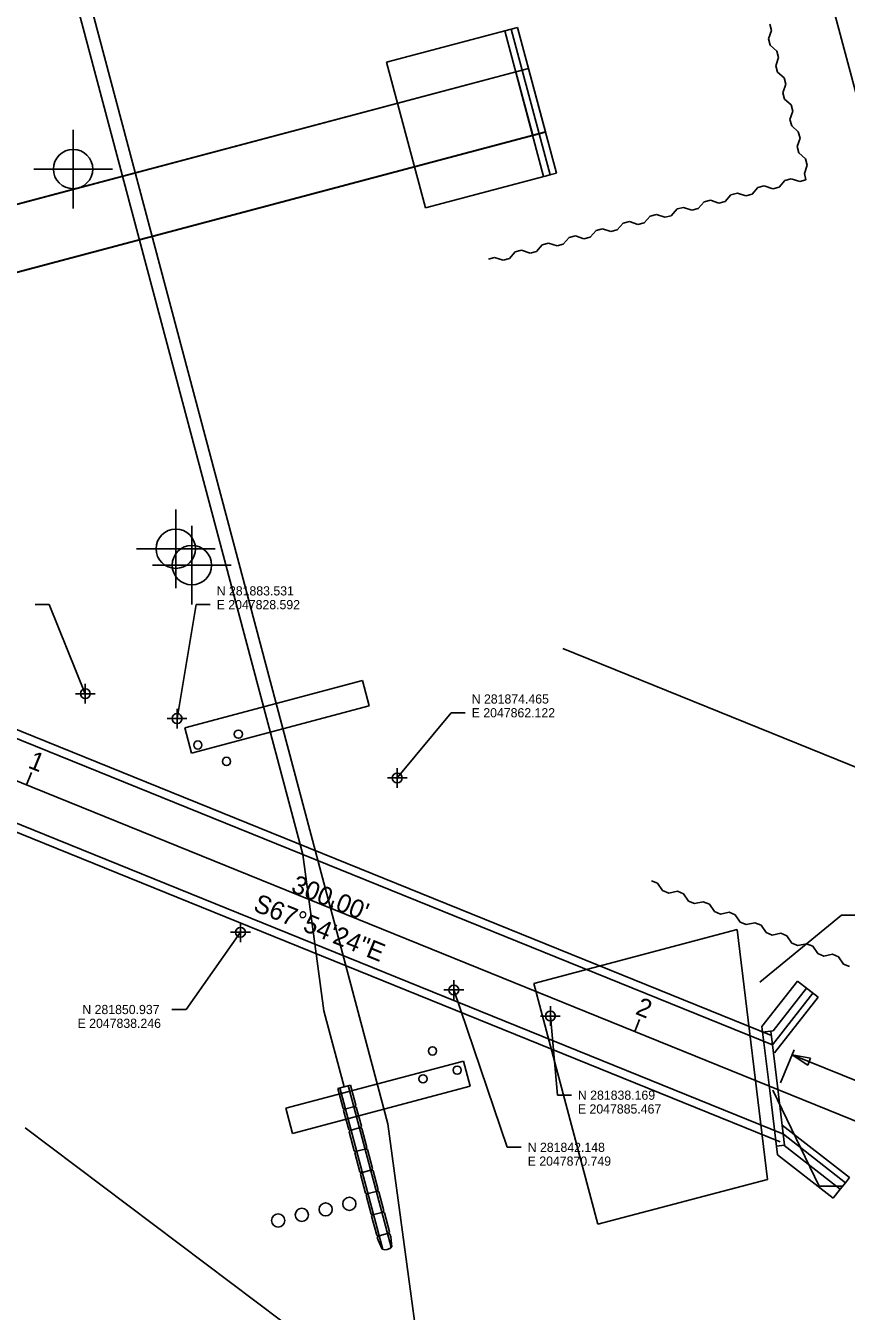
# Model space of a CAD drawing. Extents: x 2047712 to 2051245, y 280285 to 283042.
# Drawn here: x 2047805.5 to 2047930.5, y 281793.2 to 281989.1 of the extents above; entities that cross this region are included whole.
import ezdxf

# ---------------------------------------------------------------- set-up
doc = ezdxf.new("R2010")
doc.units = 0
for name, color, linetype in [('DV_X_Property_Line', 7, 'Continuous'), ('DV_X_Text', 7, 'Continuous'), ('RD_X_Cells', 7, 'Continuous'), ('RD_X_Concrete_Pad', 7, 'Continuous'), ('RD_X_GR_Lt', 7, 'Continuous'), ('RD_X_GR_Rt', 7, 'Continuous'), ('RW_X_CL_100_Cardinal_Points', 7, 'Continuous'), ('RW_X_CL_100_Curve_Data', 7, 'Continuous'), ('RW_X_CL_100_Distances', 7, 'Continuous'), ('RW_X_Esmt_SH', 7, 'Continuous'), ('SC_Scratch1', 7, 'Continuous'), ('SH_Data', 7, 'Continuous'), ('SV_Control_Point', 7, 'Continuous'), ('SV_X_Mon_Cells_Found', 7, 'Continuous'), ('SV_X_Text', 7, 'Continuous'), ('TopoDOT_Transients', 7, 'Continuous')]:
    doc.layers.add(name, color=color, linetype=linetype)

msp = doc.modelspace()

# ---------------------------------------------------------------- linework, layer by layer
at = {"layer": 'RD_X_Cells'}
for p, q in [((2047805.64, 281873.43), (2047806.39, 281875.28)), ((2047851.97, 281854.62), (2047852.42, 281855.74)), ((2047898.3, 281835.82), (2047899.05, 281837.67))]:
    msp.add_line(p, q, dxfattribs=at)
at = {"layer": 'RD_X_Concrete_Pad'}
for p, q in [((2047809.11, 281900.89), (2047806.97, 281900.89)), ((2047809.11, 281900.89), (2047814.61, 281887.31)), ((2047828.59, 281883.53), (2047831.51, 281900.89)), ((2047831.51, 281900.89), (2047833.65, 281900.89)), ((2047862.12, 281874.47), (2047870.36, 281884.41)), ((2047870.36, 281884.41), (2047872.5, 281884.41)), ((2047917.37, 281843.35), (2047929.82, 281853.53)), ((2047933.35, 281853.53), (2047929.82, 281853.53)), ((2047829.95, 281839.17), (2047838.25, 281850.94)), ((2047878.89, 281818.16), (2047870.75, 281842.15)), ((2047829.95, 281839.17), (2047827.81, 281839.17)), ((2047886.54, 281826.11), (2047885.47, 281838.17)), ((2047919.37, 281826.89), (2047926.42, 281812.25)), ((2047886.54, 281826.11), (2047888.68, 281826.11)), ((2047878.89, 281818.16), (2047881.03, 281818.16)), ((2047929.94, 281812.25), (2047926.42, 281812.25))]:
    msp.add_line(p, q, dxfattribs=at)
at = {"layer": 'RD_X_GR_Lt'}
for p, q in [((2047828.39, 281909.42), (2047828.39, 281915.42)), ((2047828.39, 281912.42), (2047828.39, 281909.42)), ((2047828.39, 281909.42), (2047822.39, 281909.42)), ((2047828.39, 281909.42), (2047825.39, 281909.42)), ((2047828.39, 281909.42), (2047828.39, 281903.42)), ((2047828.39, 281909.42), (2047834.39, 281909.42)), ((2047828.39, 281906.42), (2047828.39, 281909.42)), ((2047828.39, 281909.42), (2047831.39, 281909.42)), ((2047814.61, 281887.31), (2047814.61, 281888.81)), ((2047814.61, 281888.06), (2047814.61, 281887.31)), ((2047814.61, 281887.31), (2047813.11, 281887.31)), ((2047814.61, 281887.31), (2047813.86, 281887.31)), ((2047814.61, 281887.31), (2047814.61, 281885.81)), ((2047814.61, 281887.31), (2047816.11, 281887.31)), ((2047814.61, 281886.56), (2047814.61, 281887.31)), ((2047814.61, 281887.31), (2047815.36, 281887.31)), ((2047828.59, 281883.53), (2047828.59, 281885.03)), ((2047828.59, 281884.28), (2047828.59, 281883.53)), ((2047828.59, 281883.53), (2047827.09, 281883.53)), ((2047828.59, 281883.53), (2047827.84, 281883.53)), ((2047828.59, 281883.53), (2047828.59, 281882.03)), ((2047828.59, 281883.53), (2047830.09, 281883.53)), ((2047828.59, 281882.78), (2047828.59, 281883.53)), ((2047828.59, 281883.53), (2047829.34, 281883.53)), ((2047862.12, 281874.47), (2047862.12, 281875.97)), ((2047862.12, 281874.47), (2047860.62, 281874.47)), ((2047862.12, 281874.47), (2047861.37, 281874.47)), ((2047862.12, 281875.22), (2047862.12, 281874.47)), ((2047862.12, 281874.47), (2047862.12, 281872.97)), ((2047862.12, 281874.47), (2047863.62, 281874.47)), ((2047862.12, 281873.72), (2047862.12, 281874.47)), ((2047862.12, 281874.47), (2047862.87, 281874.47))]:
    msp.add_line(p, q, dxfattribs=at)
for centre, radius in [((2047828.39, 281909.42), 3), ((2047814.61, 281887.31), 0.75), ((2047828.59, 281883.53), 0.75), ((2047862.12, 281874.47), 0.75)]:
    msp.add_circle(centre, radius, dxfattribs=at)
for centre, radius, start, end in [((2047828.39, 281909.42), 3, 90, 180), ((2047828.39, 281909.42), 3, 270, 360), ((2047814.61, 281887.31), 0.75, 90, 180), ((2047814.61, 281887.31), 0.75, 270, 360), ((2047828.59, 281883.53), 0.75, 90, 180), ((2047828.59, 281883.53), 0.75, 270, 360), ((2047862.12, 281874.47), 0.75, 90, 180), ((2047862.12, 281874.47), 0.75, 270, 360)]:
    msp.add_arc(centre, radius, start, end, dxfattribs=at)
at = {"layer": 'RD_X_GR_Rt'}
for p, q in [((2047887.35, 281894.22), (2048031.58, 281835.68)), ((2047920.53, 281827.98), (2047922.58, 281833.03)), ((2047922.28, 281832.28), (2048014.94, 281794.67))]:
    msp.add_line(p, q, dxfattribs=at)
msp.add_lwpolyline([(2047925.08, 281831.75), (2047924.66, 281830.71), (2047922.28, 281832.28)], close=True, dxfattribs=at)
at = {"layer": 'RW_X_CL_100_Cardinal_Points'}
for p, q in [((2047812.74, 281967.3), (2047812.74, 281973.3)), ((2047812.74, 281970.3), (2047812.74, 281967.3)), ((2047812.74, 281967.3), (2047806.74, 281967.3)), ((2047812.74, 281967.3), (2047809.74, 281967.3)), ((2047812.74, 281967.3), (2047812.74, 281961.3)), ((2047812.74, 281967.3), (2047818.74, 281967.3)), ((2047812.74, 281964.3), (2047812.74, 281967.3)), ((2047812.74, 281967.3), (2047815.74, 281967.3)), ((2047830.84, 281906.92), (2047830.84, 281912.92)), ((2047830.84, 281909.92), (2047830.84, 281906.92)), ((2047830.84, 281906.92), (2047824.84, 281906.92)), ((2047830.84, 281906.92), (2047827.84, 281906.92)), ((2047830.84, 281906.92), (2047830.84, 281900.92)), ((2047830.84, 281906.92), (2047836.84, 281906.92)), ((2047830.84, 281903.92), (2047830.84, 281906.92)), ((2047830.84, 281906.92), (2047833.84, 281906.92)), ((2047838.25, 281850.94), (2047838.25, 281852.44)), ((2047838.25, 281850.94), (2047836.75, 281850.94)), ((2047838.25, 281850.94), (2047837.5, 281850.94)), ((2047838.25, 281851.69), (2047838.25, 281850.94)), ((2047838.25, 281850.94), (2047838.25, 281849.44)), ((2047838.25, 281850.94), (2047839.75, 281850.94)), ((2047838.25, 281850.19), (2047838.25, 281850.94)), ((2047838.25, 281850.94), (2047839, 281850.94)), ((2047870.75, 281842.15), (2047870.75, 281843.65)), ((2047870.75, 281842.9), (2047870.75, 281842.15)), ((2047870.75, 281842.15), (2047869.25, 281842.15)), ((2047870.75, 281842.15), (2047870, 281842.15)), ((2047870.75, 281842.15), (2047870.75, 281840.65)), ((2047870.75, 281842.15), (2047872.25, 281842.15)), ((2047870.75, 281841.4), (2047870.75, 281842.15)), ((2047870.75, 281842.15), (2047871.5, 281842.15)), ((2047885.47, 281838.17), (2047885.47, 281839.67)), ((2047885.47, 281838.92), (2047885.47, 281838.17)), ((2047885.47, 281838.17), (2047883.97, 281838.17)), ((2047885.47, 281838.17), (2047884.72, 281838.17)), ((2047885.47, 281838.17), (2047885.47, 281836.67)), ((2047885.47, 281838.17), (2047886.97, 281838.17)), ((2047885.47, 281837.42), (2047885.47, 281838.17)), ((2047885.47, 281838.17), (2047886.22, 281838.17))]:
    msp.add_line(p, q, dxfattribs=at)
for centre, radius in [((2047812.74, 281967.3), 3), ((2047830.84, 281906.92), 3), ((2047838.25, 281850.94), 0.75), ((2047870.75, 281842.15), 0.75), ((2047885.47, 281838.17), 0.75)]:
    msp.add_circle(centre, radius, dxfattribs=at)
for centre, radius, start, end in [((2047812.74, 281967.3), 3, 90, 180), ((2047812.74, 281967.3), 3, 270, 360), ((2047830.84, 281906.92), 3, 90, 180), ((2047830.84, 281906.92), 3, 270, 360), ((2047838.25, 281850.94), 0.75, 90, 180), ((2047838.25, 281850.94), 0.75, 270, 360), ((2047870.75, 281842.15), 0.75, 90, 180), ((2047870.75, 281842.15), 0.75, 270, 360), ((2047885.47, 281838.17), 0.75, 90, 180), ((2047885.47, 281838.17), 0.75, 270, 360)]:
    msp.add_arc(centre, radius, start, end, dxfattribs=at)
at = {"layer": 'RW_X_CL_100_Curve_Data'}
for p, q in [((2047878.53, 281988.39), (2047880.46, 281988.9)), ((2047878.53, 281988.39), (2047884.43, 281966.16)), ((2047879.5, 281988.64), (2047885.4, 281966.41)), ((2047880.46, 281988.9), (2047886.37, 281966.67)), ((2047766.15, 281951.84), (2047882.13, 281982.63)), ((2047766.15, 281951.82), (2047882.13, 281982.62)), ((2047882.76, 281972.44), (2047880.2, 281982.1)), ((2047884.7, 281972.95), (2047882.13, 281982.62)), ((2047768.72, 281942.16), (2047884.7, 281972.95)), ((2047768.72, 281942.14), (2047884.7, 281972.93)), ((2047884.43, 281966.16), (2047886.37, 281966.67))]:
    msp.add_line(p, q, dxfattribs=at)
at = {"layer": 'RW_X_CL_100_Distances'}
for p, q in [((2047801.42, 282044.99), (2047860.7, 281821.73)), ((2047810.78, 282001.95), (2047847.73, 281862.78)), ((2047847.73, 281862.78), (2047850.94, 281838.99)), ((2047850.94, 281838.99), (2047854.02, 281827.39)), ((2047854.99, 281827.65), (2047853.06, 281827.14)), ((2047853.87, 281824.08), (2047853.06, 281827.14)), ((2047859.92, 281802.59), (2047853.38, 281827.22)), ((2047854.67, 281827.57), (2047861.21, 281802.93)), ((2047855.8, 281824.59), (2047854.99, 281827.65)), ((2047853.87, 281824.08), (2047854.07, 281823.96)), ((2047854.07, 281823.96), (2047853.96, 281823.75)), ((2047854.73, 281820.86), (2047853.96, 281823.75)), ((2047855.68, 281824.39), (2047854.07, 281823.96)), ((2047855.8, 281824.59), (2047855.68, 281824.39)), ((2047855.68, 281824.39), (2047855.89, 281824.27)), ((2047856.66, 281821.37), (2047855.89, 281824.27)), ((2047856.54, 281821.16), (2047854.93, 281820.74)), ((2047856.66, 281821.37), (2047856.54, 281821.16)), ((2047856.54, 281821.16), (2047856.74, 281821.05)), ((2047857.51, 281818.15), (2047856.74, 281821.05)), ((2047876.59, 281704.89), (2047860.7, 281821.73)), ((2047854.73, 281820.86), (2047854.93, 281820.74)), ((2047854.93, 281820.74), (2047854.81, 281820.53)), ((2047855.58, 281817.63), (2047854.81, 281820.53)), ((2047855.58, 281817.63), (2047855.78, 281817.52)), ((2047855.78, 281817.52), (2047855.67, 281817.31)), ((2047856.44, 281814.41), (2047855.67, 281817.31)), ((2047857.4, 281817.94), (2047855.78, 281817.52)), ((2047857.51, 281818.15), (2047857.4, 281817.94)), ((2047857.4, 281817.94), (2047857.6, 281817.82)), ((2047858.37, 281814.92), (2047857.6, 281817.82)), ((2047856.44, 281814.41), (2047856.64, 281814.29)), ((2047856.64, 281814.29), (2047856.52, 281814.09)), ((2047857.29, 281811.19), (2047856.52, 281814.09)), ((2047858.25, 281814.72), (2047856.64, 281814.29)), ((2047858.37, 281814.92), (2047858.25, 281814.72)), ((2047858.25, 281814.72), (2047858.45, 281814.6)), ((2047859.22, 281811.7), (2047858.45, 281814.6)), ((2047857.29, 281811.19), (2047857.5, 281811.07)), ((2047859.11, 281811.5), (2047857.5, 281811.07)), ((2047859.22, 281811.7), (2047859.11, 281811.5)), ((2047859.11, 281811.5), (2047859.31, 281811.38)), ((2047859.31, 281811.38), (2047860.08, 281808.48)), ((2047857.5, 281811.07), (2047857.38, 281810.87)), ((2047858.15, 281807.97), (2047857.38, 281810.87)), ((2047858.15, 281807.97), (2047858.35, 281807.85)), ((2047858.35, 281807.85), (2047858.23, 281807.65)), ((2047859, 281804.75), (2047858.23, 281807.65)), ((2047859.96, 281808.28), (2047858.35, 281807.85)), ((2047860.08, 281808.48), (2047859.96, 281808.28)), ((2047859.96, 281808.28), (2047860.17, 281808.16)), ((2047860.17, 281808.16), (2047860.94, 281805.26)), ((2047860.94, 281805.26), (2047860.82, 281805.06)), ((2047859, 281804.75), (2047859.21, 281804.63)), ((2047859.21, 281804.63), (2047859.09, 281804.42)), ((2047859.2, 281804), (2047859.09, 281804.42)), ((2047859.2, 281804), (2047859.83, 281802.62)), ((2047860.82, 281805.06), (2047859.21, 281804.63)), ((2047860.82, 281805.06), (2047861.02, 281804.94)), ((2047861.02, 281804.94), (2047861.13, 281804.52)), ((2047861.13, 281804.52), (2047861.28, 281803))]:
    msp.add_line(p, q, dxfattribs=at)
for centre in [(2047851.22, 281808.7), (2047854.83, 281809.55), (2047843.99, 281807.01), (2047847.6, 281807.86)]:
    msp.add_circle(centre, 1, dxfattribs=at)
msp.add_arc((2047860.27, 281803.88), 1.34, 250.6941, 319.0454, dxfattribs=at)
at = {"layer": 'RW_X_Esmt_SH'}
for p, q in [((2047918.69, 281987.15), (2047919.13, 281988.43)), ((2047919.13, 281988.43), (2047918.87, 281989.4)), ((2047918.95, 281986.18), (2047918.69, 281987.15)), ((2047919.96, 281985.29), (2047918.95, 281986.18)), ((2047919.78, 281983.04), (2047920.22, 281984.32)), ((2047920.22, 281984.32), (2047919.96, 281985.29)), ((2047920.04, 281982.08), (2047919.78, 281983.04)), ((2047921.05, 281981.18), (2047920.04, 281982.08)), ((2047920.87, 281978.94), (2047921.31, 281980.22)), ((2047921.31, 281980.22), (2047921.05, 281981.18)), ((2047921.13, 281977.97), (2047920.87, 281978.94)), ((2047922.14, 281977.07), (2047921.13, 281977.97)), ((2047921.96, 281974.83), (2047922.4, 281976.11)), ((2047922.4, 281976.11), (2047922.14, 281977.07)), ((2047922.22, 281973.86), (2047921.96, 281974.83)), ((2047923.23, 281972.97), (2047922.22, 281973.86)), ((2047923.06, 281970.72), (2047923.49, 281972)), ((2047923.49, 281972), (2047923.23, 281972.97)), ((2047923.31, 281969.75), (2047923.06, 281970.72)), ((2047924.33, 281968.86), (2047923.31, 281969.75)), ((2047924.58, 281967.89), (2047924.33, 281968.86)), ((2047924.15, 281966.61), (2047924.58, 281967.89)), ((2047924.4, 281965.65), (2047924.15, 281966.61)), ((2047917.08, 281964.48), (2047916.19, 281963.46)), ((2047918.05, 281964.74), (2047917.08, 281964.48)), ((2047919.33, 281964.3), (2047918.05, 281964.74)), ((2047920.29, 281964.56), (2047919.33, 281964.3)), ((2047921.19, 281965.57), (2047920.29, 281964.56)), ((2047922.16, 281965.83), (2047921.19, 281965.57)), ((2047923.44, 281965.39), (2047922.16, 281965.83)), ((2047924.4, 281965.65), (2047923.44, 281965.39)), ((2047908.87, 281962.3), (2047907.97, 281961.28)), ((2047909.83, 281962.55), (2047908.87, 281962.3)), ((2047911.11, 281962.12), (2047909.83, 281962.55)), ((2047912.08, 281962.37), (2047911.11, 281962.12)), ((2047912.97, 281963.39), (2047912.08, 281962.37)), ((2047913.94, 281963.64), (2047912.97, 281963.39)), ((2047915.22, 281963.21), (2047913.94, 281963.64)), ((2047916.19, 281963.46), (2047915.22, 281963.21)), ((2047900.65, 281960.12), (2047899.76, 281959.1)), ((2047901.62, 281960.37), (2047900.65, 281960.12)), ((2047902.9, 281959.94), (2047901.62, 281960.37)), ((2047903.86, 281960.19), (2047902.9, 281959.94)), ((2047904.76, 281961.21), (2047903.86, 281960.19)), ((2047905.73, 281961.46), (2047904.76, 281961.21)), ((2047907.01, 281961.03), (2047905.73, 281961.46)), ((2047907.97, 281961.28), (2047907.01, 281961.03)), ((2047893.4, 281958.19), (2047892.44, 281957.93)), ((2047894.68, 281957.76), (2047893.4, 281958.19)), ((2047896.54, 281959.03), (2047895.65, 281958.01)), ((2047897.51, 281959.28), (2047896.54, 281959.03)), ((2047898.79, 281958.85), (2047897.51, 281959.28)), ((2047899.76, 281959.1), (2047898.79, 281958.85)), ((2047888.33, 281956.84), (2047887.43, 281955.83)), ((2047889.29, 281957.1), (2047888.33, 281956.84)), ((2047890.57, 281956.66), (2047889.29, 281957.1)), ((2047891.54, 281956.92), (2047890.57, 281956.66)), ((2047892.44, 281957.93), (2047891.54, 281956.92)), ((2047895.65, 281958.01), (2047894.68, 281957.76)), ((2047880.11, 281954.66), (2047879.22, 281953.65)), ((2047881.08, 281954.92), (2047880.11, 281954.66)), ((2047882.36, 281954.48), (2047881.08, 281954.92)), ((2047883.33, 281954.74), (2047882.36, 281954.48)), ((2047884.22, 281955.75), (2047883.33, 281954.74)), ((2047885.19, 281956.01), (2047884.22, 281955.75)), ((2047886.47, 281955.57), (2047885.19, 281956.01)), ((2047887.43, 281955.83), (2047886.47, 281955.57)), ((2047876.97, 281953.83), (2047876.01, 281953.57)), ((2047878.25, 281953.39), (2047876.97, 281953.83)), ((2047879.22, 281953.65), (2047878.25, 281953.39))]:
    msp.add_line(p, q, dxfattribs=at)
at = {"layer": 'SC_Scratch1'}
msp.add_line((2047712.98, 281911.04), (2047990.95, 281798.21), dxfattribs=at)
at = {"layer": 'SH_Data'}
for p, q in [((2047784.22, 281889.91), (2047919.12, 281835.19)), ((2047781.95, 281889.48), (2047919.29, 281833.77)), ((2047920.95, 281820.15), (2047786.48, 281874.73)), ((2047920.48, 281818.99), (2047786.01, 281873.57)), ((2047917.69, 281836.59), (2047923.09, 281843.49)), ((2047923.09, 281843.49), (2047926.24, 281841.03)), ((2047919.29, 281833.77), (2047925.45, 281841.64)), ((2047919.39, 281835.92), (2047924.47, 281842.41)), ((2047919.61, 281832.56), (2047926.24, 281841.03)), ((2047918.88, 281826.81), (2047917.69, 281836.59)), ((2047917.79, 281835.73), (2047919.39, 281835.92)), ((2047920.1, 281827.08), (2047919.03, 281835.88)), ((2047921.15, 281818.51), (2047920.1, 281827.08)), ((2047920.07, 281817.03), (2047918.88, 281826.81)), ((2047931.01, 281813.54), (2047920.78, 281821.55)), ((2047930.4, 281812.75), (2047920.95, 281820.15)), ((2047919.91, 281818.35), (2047921.15, 281818.51)), ((2047928.55, 281810.39), (2047920.07, 281817.03)), ((2047929.62, 281811.77), (2047921.03, 281818.49)), ((2047928.55, 281810.39), (2047929.62, 281811.77))]:
    msp.add_line(p, q, dxfattribs=at)
at = {"layer": 'SV_Control_Point'}
for p, q in [((2047936.73, 281961.09), (2047922.3, 282015.45)), ((2047805.42, 281821.12), (2047850.83, 281786.96))]:
    msp.add_line(p, q, dxfattribs=at)
at = {"layer": 'SV_X_Mon_Cells_Found'}
for p, q in [((2047856.82, 281889.31), (2047829.76, 281882.13)), ((2047856.82, 281889.31), (2047857.85, 281885.45)), ((2047857.85, 281885.45), (2047830.79, 281878.26)), ((2047829.76, 281882.13), (2047830.79, 281878.26)), ((2047872.22, 281831.32), (2047845.16, 281824.14)), ((2047872.22, 281831.32), (2047873.25, 281827.46)), ((2047873.25, 281827.46), (2047846.18, 281820.27)), ((2047845.16, 281824.14), (2047846.18, 281820.27)), ((2047930.4, 281812.75), (2047931.01, 281813.54)), ((2047929.62, 281811.77), (2047930.4, 281812.75))]:
    msp.add_line(p, q, dxfattribs=at)
for centre in [(2047837.93, 281881.14), (2047831.75, 281879.49), (2047836.11, 281876.99), (2047867.5, 281832.86), (2047866.06, 281828.61), (2047871.26, 281829.92)]:
    msp.add_circle(centre, 0.625, dxfattribs=at)
at = {"layer": 'SV_X_Text'}
for p, q in [((2047860.51, 281983.6), (2047879.5, 281988.64)), ((2047866.42, 281961.37), (2047860.51, 281983.6)), ((2047866.42, 281961.37), (2047885.4, 281966.41)), ((2047882.95, 281843.16), (2047913.89, 281851.37)), ((2047918.52, 281813.28), (2047913.89, 281851.37)), ((2047892.7, 281806.43), (2047882.95, 281843.16)), ((2047892.7, 281806.43), (2047918.52, 281813.28))]:
    msp.add_line(p, q, dxfattribs=at)
at = {"layer": 'TopoDOT_Transients'}
for p, q in [((2047901.8, 281858.41), (2047900.87, 281858.78)), ((2047902.56, 281857.29), (2047901.8, 281858.41)), ((2047903.49, 281856.91), (2047902.56, 281857.29)), ((2047904.81, 281857.19), (2047903.49, 281856.91)), ((2047905.74, 281856.81), (2047904.81, 281857.19)), ((2047906.5, 281855.69), (2047905.74, 281856.81)), ((2047907.42, 281855.32), (2047906.5, 281855.69)), ((2047908.75, 281855.59), (2047907.42, 281855.32)), ((2047909.68, 281855.21), (2047908.75, 281855.59)), ((2047910.44, 281854.09), (2047909.68, 281855.21)), ((2047911.36, 281853.72), (2047910.44, 281854.09)), ((2047912.69, 281853.99), (2047911.36, 281853.72)), ((2047913.61, 281853.61), (2047912.69, 281853.99)), ((2047914.37, 281852.5), (2047913.61, 281853.61)), ((2047915.3, 281852.12), (2047914.37, 281852.5)), ((2047916.63, 281852.39), (2047915.3, 281852.12)), ((2047917.55, 281852.01), (2047916.63, 281852.39)), ((2047918.31, 281850.9), (2047917.55, 281852.01)), ((2047919.24, 281850.52), (2047918.31, 281850.9)), ((2047920.56, 281850.79), (2047919.24, 281850.52)), ((2047921.49, 281850.42), (2047920.56, 281850.79)), ((2047922.25, 281849.3), (2047921.49, 281850.42)), ((2047923.18, 281848.92), (2047922.25, 281849.3)), ((2047924.5, 281849.19), (2047923.18, 281848.92)), ((2047925.43, 281848.82), (2047924.5, 281849.19)), ((2047926.19, 281847.7), (2047925.43, 281848.82)), ((2047927.11, 281847.32), (2047926.19, 281847.7)), ((2047928.44, 281847.6), (2047927.11, 281847.32)), ((2047929.37, 281847.22), (2047928.44, 281847.6)), ((2047930.13, 281846.1), (2047929.37, 281847.22)), ((2047931.05, 281845.73), (2047930.13, 281846.1))]:
    msp.add_line(p, q, dxfattribs=at)

# ---------------------------------------------------------------- texts
at = {"layer": 'DV_X_Property_Line'}
msp.add_text('S67°54\'24"E', height=2.8, rotation=337.9067, dxfattribs=at).set_placement((2047840.03, 281854.29))
at = {"layer": 'DV_X_Text'}
msp.add_text("300.00'", height=2.8, rotation=337.9067, dxfattribs=at).set_placement((2047845.79, 281857.17))
at = {"layer": 'RD_X_Cells'}
for s, p in [('1', (2047805.73, 281876.09)), ('2', (2047898.27, 281838.53))]:
    msp.add_text(s, height=2.8, rotation=337.9067, dxfattribs=at).set_placement(p)
at = {"layer": 'RD_X_Concrete_Pad'}
for s, p in [('N 281883.531', (2047834.62, 281902.29)), ('E 2047828.592', (2047834.62, 281900.19)), ('N 281874.465', (2047873.47, 281885.81)), ('E 2047862.122', (2047873.47, 281883.71)), ('N 281850.937', (2047814.15, 281838.47)), ('E 2047838.246', (2047813.43, 281836.37)), ('N 281838.169', (2047889.65, 281825.41)), ('E 2047885.467', (2047889.65, 281823.31)), ('N 281842.148', (2047882, 281817.46)), ('E 2047870.749', (2047882, 281815.36))]:
    msp.add_text(s, height=1.4, dxfattribs=at).set_placement(p)

doc.saveas('drawing.dxf')
